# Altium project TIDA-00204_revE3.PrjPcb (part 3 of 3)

## Sheet TIDA-00204_revE3_Sitara_SC_0.SchDoc: =DocumentName
size 431 x 279 mm; Date: Not shown in title block; ApprovedBy: Not shown in title block; CheckedBy: Not shown in title block; Author: Not shown in title block; CompanyName: Not shown in title block; DrawnBy: K. Mogensen; Engineer: K. Mogensen; Organization: Not shown in title block; Address1: Not shown in title block; Address2: Not shown in title block; Address3: Not shown in title block; Address4: Not shown in title block; DocumentNumber: 7; Revision: Use project parameter SCH_Rev; SheetNumber: 7; SheetTotal: 10; PageSetup: Record=PageOptions¦CenterHorizontal=True¦CenterVertical=True¦PrintScale=0.62¦XCorrection=1.00¦YCorrection=1.00¦PrintKind=0¦BorderSize=5000000¦LeftOffset=0¦BottomOffset=0¦Orientation=2¦PaperLength=1000¦PaperWidth=1000¦Scale=100¦PaperSource=15¦PrintQuality=600¦MediaType=1¦DitherType=10¦PrintScaleMode=1¦PaperKind=Letter
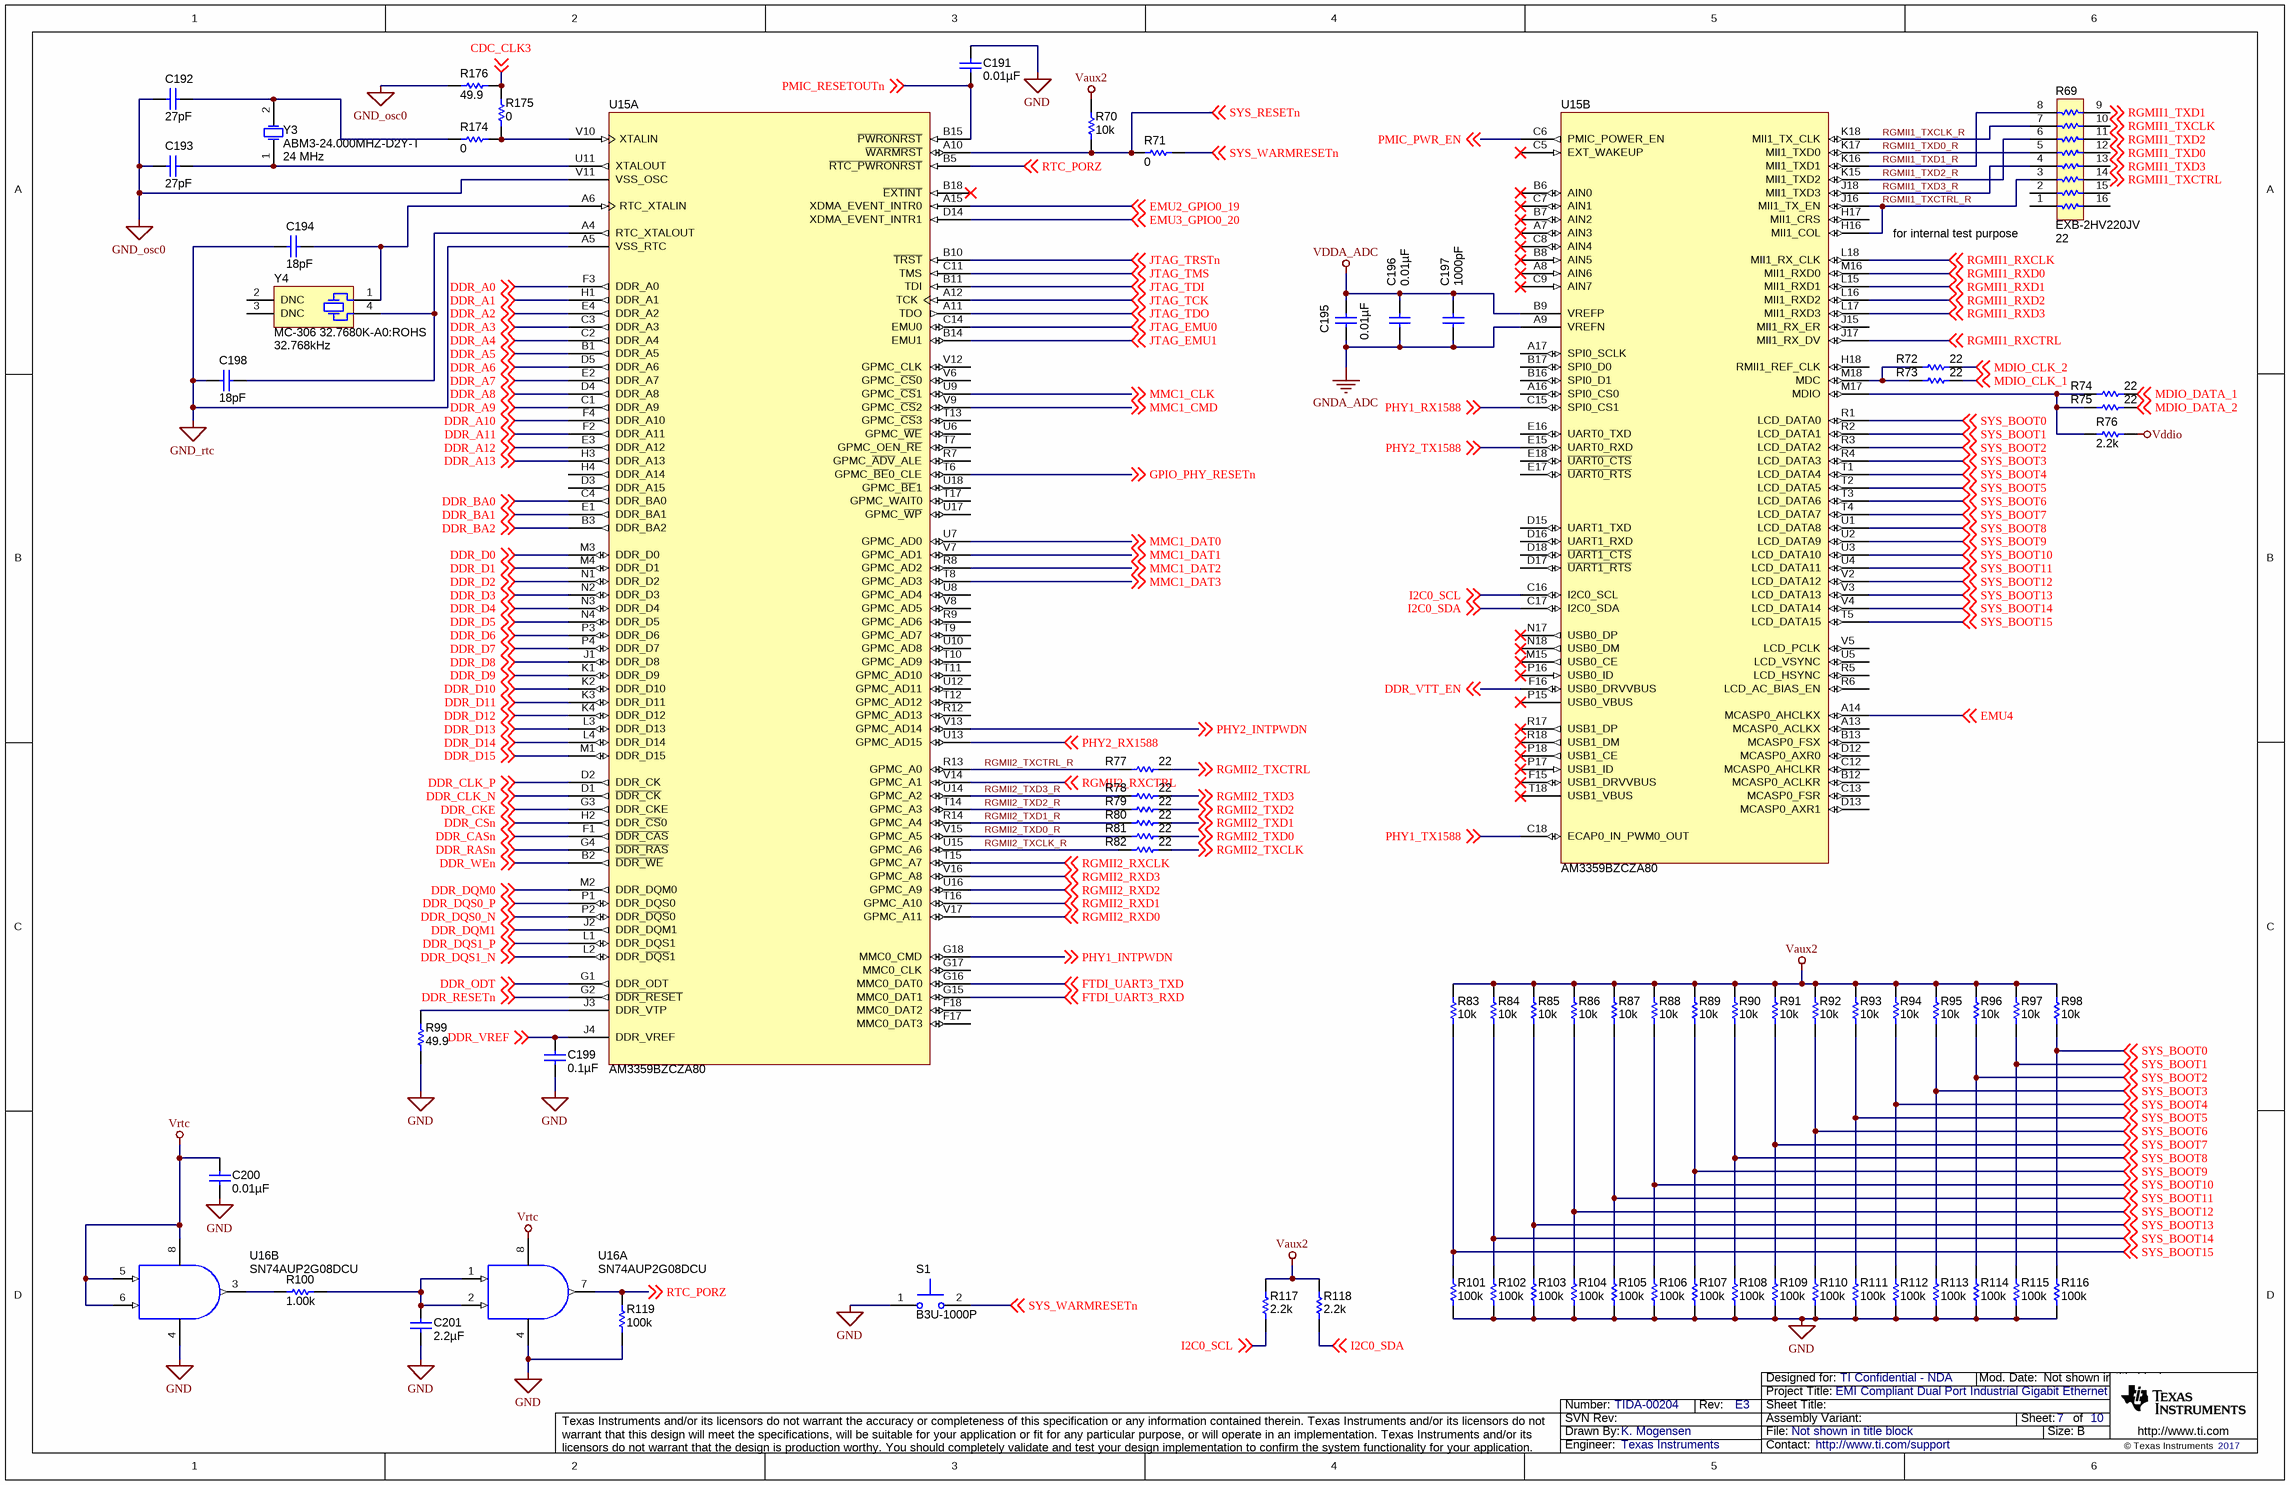
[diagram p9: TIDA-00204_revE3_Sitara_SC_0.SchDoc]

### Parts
C191  ValueDisplayed: 0.01µF  [0201]  (hidden comment: GRM033R71A103KA01D)
C192  ValueDisplayed: 27pF  [0402]  (hidden comment: GRM1555C1H270JA01D)
C193  ValueDisplayed: 27pF  [0402]  (hidden comment: GRM1555C1H270JA01D)
C194  ValueDisplayed: 18pF  [0402]  (hidden comment: GRM1555C1H180JA01D)
C195  ValueDisplayed: 0.01µF  [0201]  (hidden comment: GRM033R71A103KA01D)
C196  ValueDisplayed: 0.01µF  [0201]  (hidden comment: GRM033R71A103KA01D)
C197  ValueDisplayed: 1000pF  [0201]  (hidden comment: GRM033R71C102KA01D)
C198  ValueDisplayed: 18pF  [0402]  (hidden comment: GRM1555C1H180JA01D)
C199  ValueDisplayed: 0.1µF  [0402]  (hidden comment: GRM155R71A104KA01D)
C200  ValueDisplayed: 0.01µF  [0201]  (hidden comment: GRM033R71A103KA01D)
C201  ValueDisplayed: 2.2µF  [0603]  (hidden comment: GRM188R71A225KE15D)
R69  EXB-2HV220JV  ValueDisplayed: 22  [RESCAXS_EXB-2HV]
R70  ValueDisplayed: 10k  [0402]  (hidden comment: CRCW040210K0JNED)
R71  ValueDisplayed: 0  [0603]  (hidden comment: CRCW06030000Z0EA)
R72  ValueDisplayed: 22  [0402]  (hidden comment: CRCW040222R0JNED)
R73  ValueDisplayed: 22  [0402]  (hidden comment: CRCW040222R0JNED)
R74  ValueDisplayed: 22  [0402]  (hidden comment: CRCW040222R0JNED)
R75  ValueDisplayed: 22  [0402]  (hidden comment: CRCW040222R0JNED)
R76  ValueDisplayed: 2.2k  [0402]  (hidden comment: CRCW04022K20JNED)
R77  ValueDisplayed: 22  [0402]  (hidden comment: CRCW040222R0JNED)
R78  ValueDisplayed: 22  [0402]  (hidden comment: CRCW040222R0JNED)
R79  ValueDisplayed: 22  [0402]  (hidden comment: CRCW040222R0JNED)
R80  ValueDisplayed: 22  [0402]  (hidden comment: CRCW040222R0JNED)
R81  ValueDisplayed: 22  [0402]  (hidden comment: CRCW040222R0JNED)
R82  ValueDisplayed: 22  [0402]  (hidden comment: CRCW040222R0JNED)
R83  ValueDisplayed: 10k  [0402]  (hidden comment: CRCW040210K0JNED)
R84  ValueDisplayed: 10k  [0402]  (hidden comment: CRCW040210K0JNED)
R85  ValueDisplayed: 10k  [0402]  (hidden comment: CRCW040210K0JNED)
R86  ValueDisplayed: 10k  [0402]  (hidden comment: CRCW040210K0JNED)
R87  ValueDisplayed: 10k  [0402]  (hidden comment: CRCW040210K0JNED)
R88  ValueDisplayed: 10k  [0402]  (hidden comment: CRCW040210K0JNED)
R89  ValueDisplayed: 10k  [0402]  (hidden comment: CRCW040210K0JNED)
R90  ValueDisplayed: 10k  [0402]  (hidden comment: CRCW040210K0JNED)
R91  ValueDisplayed: 10k  [0402]  (hidden comment: CRCW040210K0JNED)
R92  ValueDisplayed: 10k  [0402]  (hidden comment: CRCW040210K0JNED)
R93  ValueDisplayed: 10k  [0402]  (hidden comment: CRCW040210K0JNED)
R94  ValueDisplayed: 10k  [0402]  (hidden comment: CRCW040210K0JNED)
R95  ValueDisplayed: 10k  [0402]  (hidden comment: CRCW040210K0JNED)
R96  ValueDisplayed: 10k  [0402]  (hidden comment: CRCW040210K0JNED)
R97  ValueDisplayed: 10k  [0402]  (hidden comment: CRCW040210K0JNED)
R98  ValueDisplayed: 10k  [0402]  (hidden comment: CRCW040210K0JNED)
R99  ValueDisplayed: 49.9  [0402]  (hidden comment: CRCW040249R9FKED)
R100  ValueDisplayed: 1.00k  [0402]  (hidden comment: CRCW04021K00FKED)
R101  ValueDisplayed: 100k  [0402]  (hidden comment: CRCW0402100KJNED)
R102  ValueDisplayed: 100k  [0402]  (hidden comment: CRCW0402100KJNED)
R103  ValueDisplayed: 100k  [0402]  (hidden comment: CRCW0402100KJNED)
R104  ValueDisplayed: 100k  [0402]  (hidden comment: CRCW0402100KJNED)
R105  ValueDisplayed: 100k  [0402]  (hidden comment: CRCW0402100KJNED)
R106  ValueDisplayed: 100k  [0402]  (hidden comment: CRCW0402100KJNED)
R107  ValueDisplayed: 100k  [0402]  (hidden comment: CRCW0402100KJNED)
R108  ValueDisplayed: 100k  [0402]  (hidden comment: CRCW0402100KJNED)
R109  ValueDisplayed: 100k  [0402]  (hidden comment: CRCW0402100KJNED)
R110  ValueDisplayed: 100k  [0402]  (hidden comment: CRCW0402100KJNED)
R111  ValueDisplayed: 100k  [0402]  (hidden comment: CRCW0402100KJNED)
R112  ValueDisplayed: 100k  [0402]  (hidden comment: CRCW0402100KJNED)
R113  ValueDisplayed: 100k  [0402]  (hidden comment: CRCW0402100KJNED)
R114  ValueDisplayed: 100k  [0402]  (hidden comment: CRCW0402100KJNED)
R115  ValueDisplayed: 100k  [0402]  (hidden comment: CRCW0402100KJNED)
R116  ValueDisplayed: 100k  [0402]  (hidden comment: CRCW0402100KJNED)
R117  ValueDisplayed: 2.2k  [0402]  (hidden comment: CRCW04022K20JNED)
R118  ValueDisplayed: 2.2k  [0402]  (hidden comment: CRCW04022K20JNED)
R119  ValueDisplayed: 100k  [0402]  (hidden comment: CRCW0402100KFKED)
R174  ValueDisplayed: 0  [0402]  (hidden comment: CRCW04020000Z0ED)
R175  ValueDisplayed: 0  [0402]  (hidden comment: CRCW04020000Z0ED)
R176  ValueDisplayed: 49.9  [0402]  (hidden comment: CRCW040249R9FKED)
S1  B3U-1000P  [SW_B3U-1000P]
U15  AM3359BZCZA80  [ZCZ0324A]  (parts A,B of 4)
U16  SN74AUP2G08DCU  [DCU0008A_N]  (parts A,B of 2)
Y3  ABM3-24.000MHZ-D2Y-T  Frequency: 24 MHz  [XTAL_ABM3]
Y4  MC-306 32.7680K-A0:ROHS  Frequency: 32.768kHz  [XTAL_MC-306]

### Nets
GND: C191.1 C199.2 C200.2 C201.2 R99.1 R101.1 R102.1 R103.1 R104.1 R105.1 R106.1 R107.1 R108.1 R109.1 R110.1 R111.1 R112.1 R113.1 R114.1 R115.1 R116.1 R119.1 S1.1 U16.4(V-)
GND_osc0: C192.2 C193.2 R176.1 U15.V11(VSS_OSC)
GND_rtc: C194.2 C198.2 U15.A5(VSS_RTC)
GNDA_ADC: C195.2 C196.2 C197.2 U15.A9(VREFN)
Vaux2: R70.2 R83.2 R84.2 R85.2 R86.2 R87.2 R88.2 R89.2 R90.2 R91.2 R92.2 R93.2 R94.2 R95.2 R96.2 R97.2 R98.2 R117.2 R118.2
VDDA_ADC: C195.1 C196.1 C197.1 U15.B9(VREFP)
Vddio: R76.2
Vrtc: C200.1 U16.5(2A) U16.6(2B) U16.8(V+)
CDC_CLK3: R175.2 R176.2 ; off-sheet CDC_CLK3
DDR_A0: U15.F3(DDR_A0) ; off-sheet DDR_A0
DDR_A1: U15.H1(DDR_A1) ; off-sheet DDR_A1
DDR_A2: U15.E4(DDR_A2) ; off-sheet DDR_A2
DDR_A3: U15.C3(DDR_A3) ; off-sheet DDR_A3
DDR_A4: U15.C2(DDR_A4) ; off-sheet DDR_A4
DDR_A5: U15.B1(DDR_A5) ; off-sheet DDR_A5
DDR_A6: U15.D5(DDR_A6) ; off-sheet DDR_A6
DDR_A7: U15.E2(DDR_A7) ; off-sheet DDR_A7
DDR_A8: U15.D4(DDR_A8) ; off-sheet DDR_A8
DDR_A9: U15.C1(DDR_A9) ; off-sheet DDR_A9
DDR_A10: U15.F4(DDR_A10) ; off-sheet DDR_A10
DDR_A11: U15.F2(DDR_A11) ; off-sheet DDR_A11
DDR_A12: U15.E3(DDR_A12) ; off-sheet DDR_A12
DDR_A13: U15.H3(DDR_A13) ; off-sheet DDR_A13
DDR_BA0: U15.C4(DDR_BA0) ; off-sheet DDR_BA0
DDR_BA1: U15.E1(DDR_BA1) ; off-sheet DDR_BA1
DDR_BA2: U15.B3(DDR_BA2) ; off-sheet DDR_BA2
DDR_CASn: U15.F1(~{DDR_CAS}) ; off-sheet DDR_CASn
DDR_CKE: U15.G3(DDR_CKE) ; off-sheet DDR_CKE
DDR_CLK_N: U15.D1(~{DDR_CK}) ; off-sheet DDR_CLK_N
DDR_CLK_P: U15.D2(DDR_CK) ; off-sheet DDR_CLK_P
DDR_CSn: U15.H2(DDR_~{CS}0) ; off-sheet DDR_CSn
DDR_D0: U15.M3(DDR_D0) ; off-sheet DDR_D0
DDR_D1: U15.M4(DDR_D1) ; off-sheet DDR_D1
DDR_D2: U15.N1(DDR_D2) ; off-sheet DDR_D2
DDR_D3: U15.N2(DDR_D3) ; off-sheet DDR_D3
DDR_D4: U15.N3(DDR_D4) ; off-sheet DDR_D4
DDR_D5: U15.N4(DDR_D5) ; off-sheet DDR_D5
DDR_D6: U15.P3(DDR_D6) ; off-sheet DDR_D6
DDR_D7: U15.P4(DDR_D7) ; off-sheet DDR_D7
DDR_D8: U15.J1(DDR_D8) ; off-sheet DDR_D8
DDR_D9: U15.K1(DDR_D9) ; off-sheet DDR_D9
DDR_D10: U15.K2(DDR_D10) ; off-sheet DDR_D10
DDR_D11: U15.K3(DDR_D11) ; off-sheet DDR_D11
DDR_D12: U15.K4(DDR_D12) ; off-sheet DDR_D12
DDR_D13: U15.L3(DDR_D13) ; off-sheet DDR_D13
DDR_D14: U15.L4(DDR_D14) ; off-sheet DDR_D14
DDR_D15: U15.M1(DDR_D15) ; off-sheet DDR_D15
DDR_DQM0: U15.M2(DDR_DQM0) ; off-sheet DDR_DQM0
DDR_DQM1: U15.J2(DDR_DQM1) ; off-sheet DDR_DQM1
DDR_DQS0_N: U15.P2(DDR_~{DQS}0) ; off-sheet DDR_DQS0_N
DDR_DQS0_P: U15.P1(DDR_DQS0) ; off-sheet DDR_DQS0_P
DDR_DQS1_N: U15.L2(DDR_~{DQS}1) ; off-sheet DDR_DQS1_N
DDR_DQS1_P: U15.L1(DDR_DQS1) ; off-sheet DDR_DQS1_P
DDR_ODT: U15.G1(DDR_ODT) ; off-sheet DDR_ODT
DDR_RASn: U15.G4(~{DDR_RAS}) ; off-sheet DDR_RASn
DDR_RESETn: U15.G2(~{DDR_RESET}) ; off-sheet DDR_RESETn
DDR_VREF: C199.1 U15.J4(DDR_VREF) ; off-sheet DDR_VREF
DDR_VTT_EN: U15.F16(USB0_DRVVBUS) ; off-sheet DDR_VTT_EN
DDR_WEn: U15.B2(~{DDR_WE}) ; off-sheet DDR_WEn
EMU2_GPIO0_19: U15.A15(XDMA_EVENT_INTR0) ; off-sheet EMU2_GPIO0_19
EMU3_GPIO0_20: U15.D14(XDMA_EVENT_INTR1) ; off-sheet EMU3_GPIO0_20
EMU4: U15.A14(MCASP0_AHCLKX) ; off-sheet EMU4
FTDI_UART3_RXD: U15.G15(MMC0_DAT1) ; off-sheet FTDI_UART3_RXD
FTDI_UART3_TXD: U15.G16(MMC0_DAT0) ; off-sheet FTDI_UART3_TXD
GPIO_PHY_RESETn: U15.T6(GPMC_~{BE}0_CLE) ; off-sheet GPIO_PHY_RESETn
I2C0_SCL: R117.1 U15.C16(I2C0_SCL) ; off-sheet I2C0_SCL
I2C0_SDA: R118.1 U15.C17(I2C0_SDA) ; off-sheet I2C0_SDA
JTAG_EMU0: U15.C14(EMU0) ; off-sheet JTAG_EMU0
JTAG_EMU1: U15.B14(EMU1) ; off-sheet JTAG_EMU1
JTAG_TCK: U15.A12(TCK) ; off-sheet JTAG_TCK
JTAG_TDI: U15.B11(TDI) ; off-sheet JTAG_TDI
JTAG_TDO: U15.A11(TDO) ; off-sheet JTAG_TDO
JTAG_TMS: U15.C11(TMS) ; off-sheet JTAG_TMS
JTAG_TRSTn: U15.B10(~{TRST}) ; off-sheet JTAG_TRSTn
MDIO_CLK_1: R73.2 ; off-sheet MDIO_CLK_1
MDIO_CLK_2: R72.2 ; off-sheet MDIO_CLK_2
MDIO_DATA_1: R74.2 ; off-sheet MDIO_DATA_1
MDIO_DATA_2: R75.2 ; off-sheet MDIO_DATA_2
MMC1_CLK: U15.U9(GPMC_~{CS}1) ; off-sheet MMC1_CLK
MMC1_CMD: U15.V9(GPMC_~{CS}2) ; off-sheet MMC1_CMD
MMC1_DAT0: U15.U7(GPMC_AD0) ; off-sheet MMC1_DAT0
MMC1_DAT1: U15.V7(GPMC_AD1) ; off-sheet MMC1_DAT1
MMC1_DAT2: U15.R8(GPMC_AD2) ; off-sheet MMC1_DAT2
MMC1_DAT3: U15.T8(GPMC_AD3) ; off-sheet MMC1_DAT3
PHY1_INTPWDN: U15.G18(MMC0_CMD) ; off-sheet PHY1_INTPWDN
PHY1_RX1588: U15.C15(SPI0_CS1) ; off-sheet PHY1_RX1588
PHY1_TX1588: U15.C18(ECAP0_IN_PWM0_OUT) ; off-sheet PHY1_TX1588
PHY2_INTPWDN: U15.V13(GPMC_AD14) ; off-sheet PHY2_INTPWDN
PHY2_RX1588: U15.U13(GPMC_AD15) ; off-sheet PHY2_RX1588
PHY2_TX1588: U15.E15(UART0_RXD) ; off-sheet PHY2_TX1588
PMIC_PWR_EN: U15.C6(PMIC_POWER_EN) ; off-sheet PMIC_PWR_EN
PMIC_RESETOUTn: C191.2 U15.B15(~{PWRONRST}) ; off-sheet PMIC_RESETOUTn
RGMII1_RXCLK: U15.L18(MII1_RX_CLK) ; off-sheet RGMII1_RXCLK
RGMII1_RXCTRL: U15.J17(MII1_RX_DV) ; off-sheet RGMII1_RXCTRL
RGMII1_RXD0: U15.M16(MII1_RXD0) ; off-sheet RGMII1_RXD0
RGMII1_RXD1: U15.L15(MII1_RXD1) ; off-sheet RGMII1_RXD1
RGMII1_RXD2: U15.L16(MII1_RXD2) ; off-sheet RGMII1_RXD2
RGMII1_RXD3: U15.L17(MII1_RXD3) ; off-sheet RGMII1_RXD3
RGMII1_TXCLK: R69.10 ; off-sheet RGMII1_TXCLK
RGMII1_TXCLK_R: R69.7 U15.K18(MII1_TX_CLK)
RGMII1_TXCTRL: R69.14 ; off-sheet RGMII1_TXCTRL
RGMII1_TXCTRL_R: R69.3 U15.H16(MII1_COL) U15.J16(MII1_TX_EN)
RGMII1_TXD0: R69.12 ; off-sheet RGMII1_TXD0
RGMII1_TXD0_R: R69.5 U15.K17(MII1_TXD0)
RGMII1_TXD1: R69.9 ; off-sheet RGMII1_TXD1
RGMII1_TXD1_R: R69.8 U15.K16(MII1_TXD1)
RGMII1_TXD2: R69.11 ; off-sheet RGMII1_TXD2
RGMII1_TXD2_R: R69.6 U15.K15(MII1_TXD2)
RGMII1_TXD3: R69.13 ; off-sheet RGMII1_TXD3
RGMII1_TXD3_R: R69.4 U15.J18(MII1_TXD3)
RGMII2_RXCLK: U15.T15(GPMC_A7) ; off-sheet RGMII2_RXCLK
RGMII2_RXCTRL: U15.V14(GPMC_A1) ; off-sheet RGMII2_RXCTRL
RGMII2_RXD0: U15.V17(GPMC_A11) ; off-sheet RGMII2_RXD0
RGMII2_RXD1: U15.T16(GPMC_A10) ; off-sheet RGMII2_RXD1
RGMII2_RXD2: U15.U16(GPMC_A9) ; off-sheet RGMII2_RXD2
RGMII2_RXD3: U15.V16(GPMC_A8) ; off-sheet RGMII2_RXD3
RGMII2_TXCLK: R82.2 ; off-sheet RGMII2_TXCLK
RGMII2_TXCLK_R: R82.1 U15.U15(GPMC_A6)
RGMII2_TXCTRL: R77.2 ; off-sheet RGMII2_TXCTRL
RGMII2_TXCTRL_R: R77.1 U15.R13(GPMC_A0)
RGMII2_TXD0: R81.2 ; off-sheet RGMII2_TXD0
RGMII2_TXD0_R: R81.1 U15.V15(GPMC_A5)
RGMII2_TXD1: R80.2 ; off-sheet RGMII2_TXD1
RGMII2_TXD1_R: R80.1 U15.R14(GPMC_A4)
RGMII2_TXD2: R79.2 ; off-sheet RGMII2_TXD2
RGMII2_TXD2_R: R79.1 U15.T14(GPMC_A3)
RGMII2_TXD3: R78.2 ; off-sheet RGMII2_TXD3
RGMII2_TXD3_R: R78.1 U15.U14(GPMC_A2)
RTC_PORZ: R119.2 U15.B5(~{RTC_PWRONRST}) U16.7(1Y) ; off-sheet RTC_PORZ
SYS_BOOT0: R98.1 R116.2 U15.R1(LCD_DATA0) ; off-sheet SYS_BOOT0
SYS_BOOT1: R97.1 R115.2 U15.R2(LCD_DATA1) ; off-sheet SYS_BOOT1
SYS_BOOT2: R96.1 R114.2 U15.R3(LCD_DATA2) ; off-sheet SYS_BOOT2
SYS_BOOT3: R95.1 R113.2 U15.R4(LCD_DATA3) ; off-sheet SYS_BOOT3
SYS_BOOT4: R94.1 R112.2 U15.T1(LCD_DATA4) ; off-sheet SYS_BOOT4
SYS_BOOT5: R93.1 R111.2 U15.T2(LCD_DATA5) ; off-sheet SYS_BOOT5
SYS_BOOT6: R92.1 R110.2 U15.T3(LCD_DATA6) ; off-sheet SYS_BOOT6
SYS_BOOT7: R91.1 R109.2 U15.T4(LCD_DATA7) ; off-sheet SYS_BOOT7
SYS_BOOT8: R90.1 R108.2 U15.U1(LCD_DATA8) ; off-sheet SYS_BOOT8
SYS_BOOT9: R89.1 R107.2 U15.U2(LCD_DATA9) ; off-sheet SYS_BOOT9
SYS_BOOT10: R88.1 R106.2 U15.U3(LCD_DATA10) ; off-sheet SYS_BOOT10
SYS_BOOT11: R87.1 R105.2 U15.U4(LCD_DATA11) ; off-sheet SYS_BOOT11
SYS_BOOT12: R86.1 R104.2 U15.V2(LCD_DATA12) ; off-sheet SYS_BOOT12
SYS_BOOT13: R85.1 R103.2 U15.V3(LCD_DATA13) ; off-sheet SYS_BOOT13
SYS_BOOT14: R84.1 R102.2 U15.V4(LCD_DATA14) ; off-sheet SYS_BOOT14
SYS_BOOT15: R83.1 R101.2 U15.T5(LCD_DATA15) ; off-sheet SYS_BOOT15
SYS_RESETn: R70.1 R71.1 U15.A10(~{WARMRST}) ; off-sheet SYS_RESETn
SYS_WARMRESETn: R71.2 S1.2 ; off-sheet SYS_WARMRESETn
NetC192_1: C192.1 R174.2 Y3.2(OSC2)
NetC193_1: C193.1 U15.U11(XTALOUT) Y3.1(OSC1)
NetC194_1: C194.1 U15.A6(RTC_XTALIN) Y4.1
NetC198_1: C198.1 U15.A4(RTC_XTALOUT) Y4.4
NetC201_1: C201.1 R100.1 U16.1(1A) U16.2(1B)
NetR72_1: R72.1 R73.1 U15.M18(MDC)
NetR74_1: R74.1 R75.1 R76.1 U15.M17(MDIO)
NetR99_2: R99.2 U15.J3(DDR_VTP)
NetR100_2: R100.2 U16.3(2Y)
NetR174_1: R174.1 R175.1 U15.V10(XTALIN)

Not connected (* = marked no-connect by the designer): R69 1 2 15 16; U15 A7(AIN3)* A8(AIN6)* A13(MCASP0_ACLKX) A16(SPI0_CS0) A17(SPI0_SCLK) B6(AIN0)* B7(AIN2)* B8(AIN5)* B12(MCASP0_ACLKR) B13(MCASP0_FSX) B16(SPI0_D1) B17(SPI0_D0) B18(~{EXTINT})* C5(EXT_WAKEUP)* C7(AIN1)* C8(AIN4)* C9(AIN7)* C12(MCASP0_AHCLKR) C13(MCASP0_FSR) D3(DDR_A15) D12(MCASP0_AXR0) D13(MCASP0_AXR1) D15(UART1_TXD) D16(UART1_RXD) D17(~{UART1_RTS}) D18(~{UART1_CTS}) E16(UART0_TXD) E17(~{UART0_RTS}) E18(~{UART0_CTS}) F15(USB1_DRVVBUS)* F17(MMC0_DAT3) F18(MMC0_DAT2) G17(MMC0_CLK) H4(DDR_A14) H17(MII1_CRS) H18(RMII1_REF_CLK) J15(MII1_RX_ER) M15(USB0_CE)* N17(USB0_DP)* N18(USB0_DM)* P15(USB0_VBUS)* P16(USB0_ID)* P17(USB1_ID)* P18(USB1_CE)* R5(LCD_HSYNC) R6(LCD_AC_BIAS_EN) R7(GPMC_~{ADV}_ALE) R9(GPMC_AD6) R12(GPMC_AD13) R17(USB1_DP)* R18(USB1_DM)* T7(GPMC_OEN_~{RE}) T9(GPMC_AD7) T10(GPMC_AD9) T11(GPMC_AD10) T12(GPMC_AD12) T13(GPMC_~{CS}3) T17(GPMC_WAIT0) T18(USB1_VBUS)* U5(LCD_VSYNC) U6(GPMC_~{WE}) U8(GPMC_AD4) U10(GPMC_AD8) U12(GPMC_AD11) U17(GPMC_~{WP}) U18(GPMC_~{BE}1) V5(LCD_PCLK) V6(GPMC_~{CS}0) V8(GPMC_AD5) V12(GPMC_CLK); Y4 2(DNC) 3(DNC)

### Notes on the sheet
- for internal test purpose

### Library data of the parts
C191 C195 C196 C200 = GRM033R71A103KA01D: CAP, CERM, 0.01 µF, 10 V, +/- 10%, X7R, 0201; Manufacturer: MuRata; Polarized: N; CompType: Capacitor; Value: 0.01uF; U/M: EA; Cap_F: 0.00000001; Tolerance_%: 10; Value1: Unknown; Value2: 10V; TaMin_C: -55; TaMax_C: 125
C192 C193 = GRM1555C1H270JA01D: CAP, CERM, 27 pF, 50 V, +/- 5%, C0G/NP0, 0402; Manufacturer: MuRata; Polarized: N; CompType: Capacitor; Value: 27pF; U/M: EA; Cap_F: 0.000000000027; Tolerance_%: 5; Value1: Unknown; VDC_V: 50; Value2: 50V; TaMin_C: -55; TaMax_C: 125
C194 C198 = GRM1555C1H180JA01D: CAP, CERM, 18 pF, 50 V, +/- 5%, C0G/NP0, 0402; Manufacturer: MuRata; Polarized: N; CompType: Capacitor; Value: 18pF; U/M: EA; Cap_F: 0.000000000018; Tolerance_%: 5; Value1: Unknown; VDC_V: 50; Value2: 50V; TaMin_C: -55; TaMax_C: 125
C197 = GRM033R71C102KA01D: CAP, CERM, 1000 pF, 16 V, +/- 10%, X7R, 0201; Manufacturer: MuRata; Polarized: N; CompType: Capacitor; Value: 1000pF; U/M: EA; Cap_F: 0.000000001; Tolerance_%: 10; Value1: Unknown; VDC_V: 16; Value2: 16V; TaMin_C: -55; TaMax_C: 125
C199 = GRM155R71A104KA01D: CAP, CERM, 0.1 µF, 10 V, +/- 10%, X7R, 0402; Manufacturer: MuRata; Polarized: N; CompType: Capacitor; Value: 0.1uF; U/M: EA; Cap_F: 0.0000001; Tolerance_%: 10; Value1: Unknown; Value2: 10V; TaMin_C: -55; TaMax_C: 125
C201 = GRM188R71A225KE15D: CAP, CERM, 2.2 µF, 10 V, +/- 10%, X7R, 0603; Manufacturer: MuRata; Polarized: N; CompType: Capacitor; Value: 2.2uF; U/M: EA; Cap_F: 0.0000022; Tolerance_%: 10; ESR_ohm: 0.009; Value1: 0.009 ohm; Value2: 10V; TaMin_C: -55; TaMax_C: 125
R69 = EXB-2HV220JV: RES, 22, 5%, 0.0625 W, Resistor Array - 8x1; Manufacturer: Panasonic; SymbolCreator: a0411947; Value: 22; Value_Code: 22R0; Tolerance_%: 5; Power_W: 0.0625; TempCo: 200 ppm/C; EIA_Code: E24; U/M: EA
R70 R83-R98 = CRCW040210K0JNED: RES, 10 k, 5%, 0.063 W, 0402; Manufacturer: Vishay-Dale; CompType: Resistor; Value: 10k; Res_ohm: 10000; Value_Code: 10k0; Tolerance_%: 5; Power_W: 0.063; Value2: 0.063W; VDC_V: 50; TempCo: 200 ppm/C; EIA_Code: E24; U/M: EA
R71 = CRCW06030000Z0EA: RES, 0, 5%, 0.1 W, 0603; Manufacturer: Vishay-Dale; CompType: Resistor; Value: 0; Value_Code: 0000; Tolerance_%: 5; Power_W: 0.1; Value2: 0.1W; VDC_V: 75; TempCo: 200 ppm/C; EIA_Code: E24; U/M: EA
R72-R75 R77-R82 = CRCW040222R0JNED: RES, 22, 5%, 0.063 W, 0402; Manufacturer: Vishay-Dale; CompType: Resistor; Value: 22; Value_Code: 22R0; Tolerance_%: 5; Power_W: 0.063; Value2: 0.063W; VDC_V: 50; TempCo: 200 ppm/C; EIA_Code: E24; U/M: EA
R76 R117 R118 = CRCW04022K20JNED: RES, 2.2 k, 5%, 0.063 W, 0402; Manufacturer: Vishay-Dale; CompType: Resistor; Value: 2.2k; Res_ohm: 2200; Value_Code: 2k20; Tolerance_%: 5; Power_W: 0.063; Value2: 0.063W; VDC_V: 50; TempCo: 200 ppm/C; EIA_Code: E24; U/M: EA
R99 R176 = CRCW040249R9FKED: RES, 49.9, 1%, 0.063 W, 0402; Manufacturer: Vishay-Dale; CompType: Resistor; Value: 49.9; Value_Code: 49R9; Tolerance_%: 1; Power_W: 0.063; Value2: 0.063W; VDC_V: 50; TempCo: 100 ppm/C; EIA_Code: E96; U/M: EA
R100 = CRCW04021K00FKED: RES, 1.00 k, 1%, 0.063 W, 0402; Manufacturer: Vishay-Dale; CompType: Resistor; Value: 1.00k; Res_ohm: 1000; Value_Code: 1k00; Tolerance_%: 1; Power_W: 0.063; Value2: 0.063W; VDC_V: 50; TempCo: 100 ppm/C; EIA_Code: E96; U/M: EA
R101-R116 = CRCW0402100KJNED: RES, 100 k, 5%, 0.063 W, 0402; Manufacturer: Vishay-Dale; CompType: Resistor; Value: 100k; Res_ohm: 100000; Tolerance_%: 5; Power_W: 0.063; Value2: 0.063W; VDC_V: 50; TempCo: 200 ppm/C; EIA_Code: E24; U/M: EA
R119 = CRCW0402100KFKED: RES, 100 k, 1%, 0.063 W, 0402; Manufacturer: Vishay-Dale; CompType: Resistor; Value: 100k; Res_ohm: 100000; Tolerance_%: 1; Power_W: 0.063; Value2: 0.063W; VDC_V: 50; TempCo: 100 ppm/C; EIA_Code: E96; U/M: EA
R174 R175 = CRCW04020000Z0ED: RES, 0, 5%, 0.063 W, 0402; Manufacturer: Vishay-Dale; CompType: Resistor; Value: 0; Value_Code: 0000; Tolerance_%: 5; Power_W: 0.063; Value2: 0.063W; VDC_V: 50; TempCo: 200 ppm/C; EIA_Code: E24; U/M: EA
S1 = B3U-1000P: SWITCH TACTILE SPST-NO 0.05A 12V; Manufacturer: Omron Electronic Components; SymbolCreator: a0412235; VDC_V: 12; SwitchFunction: Off-Mom; PositionCount: 1; CurrentRating_mA: 50
U15 = AM3359BZCZA80: Sitara Processors, ZCZ0324A; Alternate Manufacturer: None; Manufacturer: Texas Instruments; SymbolCreator: Altium; CompType: IC; U/M: EA
U16 = SN74AUP2G08DCU: LOW-POWER DUAL 2-INPUT POSITIVE-AND GATE, DCU0008A; Manufacturer: Texas Instruments; SymbolCreator: Altium; CompType: IC; U/M: EA
Y3 = ABM3-24.000MHZ-D2Y-T: Crystal, 24 MHz, 18 pF, SMD; Manufacturer: Abracon Corportation; SymbolCreator: a0412235; U/M: EA; TaMin_C: -40; TaMax_C: 85; Frequency Stability: ±30ppm
Y4 = MC-306 32.7680K-A0:ROHS: Crystal, 32.768kHz, 12.5pF, SMD; Manufacturer: Epson; SymbolCreator: a0411947; U/M: EA; TaMin_C: -40; TaMax_C: 85; Frequency Stability: ±20ppm

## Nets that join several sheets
GND: TIDA-00204_revE3_JTAGUSB (44 pins), TIDA-00204_revE3_Memory (64 pins), TIDA-00204_revE3_PHY_1 (47 pins), TIDA-00204_revE3_PHY_2 (57 pins), TIDA-00204_revE3_PS_0 (23 pins), TIDA-00204_revE3_PS_1 (17 pins), TIDA-00204_revE3_PS_2 (34 pins), TIDA-00204_revE3_Sitara_PS (129 pins), TIDA-00204_revE3_Sitara_SC_0 (24 pins)
GND_osc0: TIDA-00204_revE3_Sitara_PS (C147.2), TIDA-00204_revE3_Sitara_SC_0 (C192.2 C193.2 R176.1 U15.V11)
GNDA_ADC: TIDA-00204_revE3_Sitara_PS (C144.2 L7.1 U15.E8), TIDA-00204_revE3_Sitara_SC_0 (C195.2 C196.2 C197.2 U15.A9)
V5__DC_Sitara: TIDA-00204_revE3_PS_0 (J1.2 R3.2), TIDA-00204_revE3_PS_1 (C22.2 R8.1 R10.1 U5.4), TIDA-00204_revE3_PS_2 (20 pins)
V11phy: TIDA-00204_revE3_PHY_1 (10 pins), TIDA-00204_revE3_PHY_2 (10 pins), TIDA-00204_revE3_PS_1 (C23.1 U5.1)
V18CDC: TIDA-00204_revE3_PHY_2 (L13.1 R169.2 R177.2 R178.2), TIDA-00204_revE3_PS_2 (C260.1 U13.7)
V25phy: TIDA-00204_revE3_PHY_1 (6 pins), TIDA-00204_revE3_PHY_2 (6 pins), TIDA-00204_revE3_PS_1 (R9.2 R13.2)
Vaux1: TIDA-00204_revE3_PS_2 (C95.1 U13.46), TIDA-00204_revE3_Sitara_PS (C134.1 C135.1 U15.N16 U15.R16)
Vaux2: TIDA-00204_revE3_PS_1 (U2.5), TIDA-00204_revE3_PS_2 (C96.1 U13.48), TIDA-00204_revE3_Sitara_PS (34 pins), TIDA-00204_revE3_Sitara_SC_0 (19 pins)
Vaux33: TIDA-00204_revE3_Memory (C233.1 R135.2 R137.2 U20.10), TIDA-00204_revE3_PS_2 (C93.1 R66.2 U13.4 U13.12), TIDA-00204_revE3_Sitara_PS (C136.1 C137.1 U15.N15 U15.R15)
Vdac: TIDA-00204_revE3_PS_2 (C98.1 U13.22), TIDA-00204_revE3_Sitara_PS (12 pins)
Vdd1_smps: TIDA-00204_revE3_PS_2 (C86.1 L3.2 U13.32), TIDA-00204_revE3_Sitara_PS (14 pins)
Vdd2_smps: TIDA-00204_revE3_PS_2 (C88.1 L4.2 U13.44), TIDA-00204_revE3_Sitara_PS (35 pins)
VDDA_ADC: TIDA-00204_revE3_Sitara_PS (C144.1 L6.1 U15.D8), TIDA-00204_revE3_Sitara_SC_0 (C195.1 C196.1 C197.1 U15.B9)
Vddio: TIDA-00204_revE3_JTAGUSB (24 pins), TIDA-00204_revE3_Memory (C207.2 U19.8), TIDA-00204_revE3_PHY_1 (14 pins), TIDA-00204_revE3_PHY_2 (13 pins), TIDA-00204_revE3_PS_1 (J3.2 R12.1), TIDA-00204_revE3_Sitara_SC_0 (R76.2)
Vdds_DDR: TIDA-00204_revE3_Memory (38 pins), TIDA-00204_revE3_PS_2 (C90.1 L5.2 U13.16), TIDA-00204_revE3_Sitara_PS (29 pins)
Vdig2: TIDA-00204_revE3_PS_2 (C92.1 U13.5), TIDA-00204_revE3_Sitara_PS (12 pins)
Vmmc: TIDA-00204_revE3_Memory (11 pins), TIDA-00204_revE3_PS_2 (C94.1 U13.2), TIDA-00204_revE3_Sitara_PS (10 pins)
Vpll: TIDA-00204_revE3_PS_2 (C97.1 U13.24), TIDA-00204_revE3_Sitara_PS (L6.2)
Vrtc: TIDA-00204_revE3_PS_2 (C101.1 U14.1), TIDA-00204_revE3_Sitara_PS (C146.1 U15.D7), TIDA-00204_revE3_Sitara_SC_0 (C200.1 U16.5 U16.6 U16.8)
CDC_CLK1: TIDA-00204_revE3_PHY_1 (R171.2), TIDA-00204_revE3_PHY_2 (R182.2)
CDC_CLK3: TIDA-00204_revE3_PHY_2 (R167.2), TIDA-00204_revE3_Sitara_SC_0 (R175.2 R176.2)
DDR_A0: TIDA-00204_revE3_Memory (R128.1 U17.N3), TIDA-00204_revE3_Sitara_SC_0 (U15.F3)
DDR_A1: TIDA-00204_revE3_Memory (R128.3 U17.P7), TIDA-00204_revE3_Sitara_SC_0 (U15.H1)
DDR_A2: TIDA-00204_revE3_Memory (R133.7 U17.P3), TIDA-00204_revE3_Sitara_SC_0 (U15.E4)
DDR_A3: TIDA-00204_revE3_Memory (R133.4 U17.N2), TIDA-00204_revE3_Sitara_SC_0 (U15.C3)
DDR_A4: TIDA-00204_revE3_Memory (R128.6 U17.P8), TIDA-00204_revE3_Sitara_SC_0 (U15.C2)
DDR_A5: TIDA-00204_revE3_Memory (R133.6 U17.P2), TIDA-00204_revE3_Sitara_SC_0 (U15.B1)
DDR_A6: TIDA-00204_revE3_Memory (R130.2 U17.R8), TIDA-00204_revE3_Sitara_SC_0 (U15.D5)
DDR_A7: TIDA-00204_revE3_Memory (R130.8 U17.R2), TIDA-00204_revE3_Sitara_SC_0 (U15.E2)
DDR_A8: TIDA-00204_revE3_Memory (R130.1 U17.T8), TIDA-00204_revE3_Sitara_SC_0 (U15.D4)
DDR_A9: TIDA-00204_revE3_Memory (R130.6 U17.R3), TIDA-00204_revE3_Sitara_SC_0 (U15.C1)
DDR_A10: TIDA-00204_revE3_Memory (R130.5 U17.L7), TIDA-00204_revE3_Sitara_SC_0 (U15.F4)
DDR_A11: TIDA-00204_revE3_Memory (R130.4 U17.R7), TIDA-00204_revE3_Sitara_SC_0 (U15.F2)
DDR_A12: TIDA-00204_revE3_Memory (R128.4 U17.N7), TIDA-00204_revE3_Sitara_SC_0 (U15.E3)
DDR_A13: TIDA-00204_revE3_Memory (R130.7 U17.T3), TIDA-00204_revE3_Sitara_SC_0 (U15.H3)
DDR_BA0: TIDA-00204_revE3_Memory (R133.3 U17.M2), TIDA-00204_revE3_Sitara_SC_0 (U15.C4)
DDR_BA1: TIDA-00204_revE3_Memory (R128.5 U17.N8), TIDA-00204_revE3_Sitara_SC_0 (U15.E1)
DDR_BA2: TIDA-00204_revE3_Memory (R133.8 U17.M3), TIDA-00204_revE3_Sitara_SC_0 (U15.B3)
DDR_CASn: TIDA-00204_revE3_Memory (R133.5 U17.K3), TIDA-00204_revE3_Sitara_SC_0 (U15.F1)
DDR_CKE: TIDA-00204_revE3_Memory (R131.2 U17.K9), TIDA-00204_revE3_Sitara_SC_0 (U15.G3)
DDR_CLK_N: TIDA-00204_revE3_Memory (R127.1 U17.K7), TIDA-00204_revE3_Sitara_SC_0 (U15.D1)
DDR_CLK_P: TIDA-00204_revE3_Memory (R126.1 U17.J7), TIDA-00204_revE3_Sitara_SC_0 (U15.D2)
DDR_CSn: TIDA-00204_revE3_Memory (R133.1 U17.L2), TIDA-00204_revE3_Sitara_SC_0 (U15.H2)
DDR_D0: TIDA-00204_revE3_Memory (U17.H7), TIDA-00204_revE3_Sitara_SC_0 (U15.M3)
DDR_D1: TIDA-00204_revE3_Memory (U17.F8), TIDA-00204_revE3_Sitara_SC_0 (U15.M4)
DDR_D2: TIDA-00204_revE3_Memory (U17.G2), TIDA-00204_revE3_Sitara_SC_0 (U15.N1)
DDR_D3: TIDA-00204_revE3_Memory (U17.F2), TIDA-00204_revE3_Sitara_SC_0 (U15.N2)
DDR_D4: TIDA-00204_revE3_Memory (U17.H3), TIDA-00204_revE3_Sitara_SC_0 (U15.N3)
DDR_D5: TIDA-00204_revE3_Memory (U17.H8), TIDA-00204_revE3_Sitara_SC_0 (U15.N4)
DDR_D6: TIDA-00204_revE3_Memory (U17.E3), TIDA-00204_revE3_Sitara_SC_0 (U15.P3)
DDR_D7: TIDA-00204_revE3_Memory (U17.F7), TIDA-00204_revE3_Sitara_SC_0 (U15.P4)
DDR_D8: TIDA-00204_revE3_Memory (U17.C3), TIDA-00204_revE3_Sitara_SC_0 (U15.J1)
DDR_D9: TIDA-00204_revE3_Memory (U17.C2), TIDA-00204_revE3_Sitara_SC_0 (U15.K1)
DDR_D10: TIDA-00204_revE3_Memory (U17.D7), TIDA-00204_revE3_Sitara_SC_0 (U15.K2)
DDR_D11: TIDA-00204_revE3_Memory (U17.C8), TIDA-00204_revE3_Sitara_SC_0 (U15.K3)
DDR_D12: TIDA-00204_revE3_Memory (U17.A3), TIDA-00204_revE3_Sitara_SC_0 (U15.K4)
DDR_D13: TIDA-00204_revE3_Memory (U17.A2), TIDA-00204_revE3_Sitara_SC_0 (U15.L3)
DDR_D14: TIDA-00204_revE3_Memory (U17.A7), TIDA-00204_revE3_Sitara_SC_0 (U15.L4)
DDR_D15: TIDA-00204_revE3_Memory (U17.B8), TIDA-00204_revE3_Sitara_SC_0 (U15.M1)
DDR_DQM0: TIDA-00204_revE3_Memory (U17.E7), TIDA-00204_revE3_Sitara_SC_0 (U15.M2)
DDR_DQM1: TIDA-00204_revE3_Memory (U17.D3), TIDA-00204_revE3_Sitara_SC_0 (U15.J2)
DDR_DQS0_N: TIDA-00204_revE3_Memory (U17.G3), TIDA-00204_revE3_Sitara_SC_0 (U15.P2)
DDR_DQS0_P: TIDA-00204_revE3_Memory (U17.F3), TIDA-00204_revE3_Sitara_SC_0 (U15.P1)
DDR_DQS1_N: TIDA-00204_revE3_Memory (U17.B7), TIDA-00204_revE3_Sitara_SC_0 (U15.L2)
DDR_DQS1_P: TIDA-00204_revE3_Memory (U17.C7), TIDA-00204_revE3_Sitara_SC_0 (U15.L1)
DDR_ODT: TIDA-00204_revE3_Memory (R133.2 U17.K1), TIDA-00204_revE3_Sitara_SC_0 (U15.G1)
DDR_RASn: TIDA-00204_revE3_Memory (R134.1 U17.J3), TIDA-00204_revE3_Sitara_SC_0 (U15.G4)
DDR_RESETn: TIDA-00204_revE3_Memory (R129.1 U17.T2), TIDA-00204_revE3_Sitara_SC_0 (U15.G2)
DDR_VREF: TIDA-00204_revE3_Memory (6 pins), TIDA-00204_revE3_Sitara_SC_0 (C199.1 U15.J4)
DDR_VTT_EN: TIDA-00204_revE3_Memory (R137.1 U20.7), TIDA-00204_revE3_Sitara_SC_0 (U15.F16)
DDR_WEn: TIDA-00204_revE3_Memory (R128.2 U17.L3), TIDA-00204_revE3_Sitara_SC_0 (U15.B2)
EMU2_GPIO0_19: TIDA-00204_revE3_JTAGUSB (R161.1), TIDA-00204_revE3_Sitara_SC_0 (U15.A15)
EMU3_GPIO0_20: TIDA-00204_revE3_JTAGUSB (R162.1), TIDA-00204_revE3_Sitara_SC_0 (U15.D14)
EMU4: TIDA-00204_revE3_JTAGUSB (R163.1), TIDA-00204_revE3_Sitara_SC_0 (U15.A14)
FTDI_UART3_RXD: TIDA-00204_revE3_JTAGUSB (U22.38), TIDA-00204_revE3_Sitara_SC_0 (U15.G15)
FTDI_UART3_TXD: TIDA-00204_revE3_JTAGUSB (U22.39), TIDA-00204_revE3_Sitara_SC_0 (U15.G16)
GPIO_PHY_RESETn: TIDA-00204_revE3_PHY_1 (R38.1 U11.1), TIDA-00204_revE3_Sitara_SC_0 (U15.T6)
I2C0_SCL: TIDA-00204_revE3_Memory (U19.6), TIDA-00204_revE3_PS_2 (U13.9), TIDA-00204_revE3_Sitara_SC_0 (R117.1 U15.C16)
I2C0_SDA: TIDA-00204_revE3_Memory (U19.5), TIDA-00204_revE3_PS_2 (U13.8), TIDA-00204_revE3_Sitara_SC_0 (R118.1 U15.C17)
JTAG_EMU0: TIDA-00204_revE3_JTAGUSB (J8.13 R144.2 R152.1), TIDA-00204_revE3_Sitara_SC_0 (U15.C14)
JTAG_EMU1: TIDA-00204_revE3_JTAGUSB (J8.14 R146.1 R147.2), TIDA-00204_revE3_Sitara_SC_0 (U15.B14)
JTAG_TCK: TIDA-00204_revE3_JTAGUSB (R139.2 R159.1 R160.1), TIDA-00204_revE3_Sitara_SC_0 (U15.A12)
JTAG_TDI: TIDA-00204_revE3_JTAGUSB (J8.3 R140.2), TIDA-00204_revE3_Sitara_SC_0 (U15.B11)
JTAG_TDO: TIDA-00204_revE3_JTAGUSB (J8.7 R141.2), TIDA-00204_revE3_Sitara_SC_0 (U15.A11)
JTAG_TMS: TIDA-00204_revE3_JTAGUSB (J8.1 R142.2), TIDA-00204_revE3_Sitara_SC_0 (U15.C11)
JTAG_TRSTn: TIDA-00204_revE3_JTAGUSB (J8.2 R143.2 R153.2), TIDA-00204_revE3_Sitara_SC_0 (U15.B10)
MDIO_CLK_1: TIDA-00204_revE3_PHY_1 (U6.20), TIDA-00204_revE3_Sitara_SC_0 (R73.2)
MDIO_CLK_2: TIDA-00204_revE3_PHY_2 (U12.20), TIDA-00204_revE3_Sitara_SC_0 (R72.2)
MDIO_DATA_1: TIDA-00204_revE3_PHY_1 (U6.21), TIDA-00204_revE3_Sitara_SC_0 (R74.2)
MDIO_DATA_2: TIDA-00204_revE3_PHY_2 (U12.21), TIDA-00204_revE3_Sitara_SC_0 (R75.2)
MMC1_CLK: TIDA-00204_revE3_Memory (J6.5 R123.1 U18.8), TIDA-00204_revE3_Sitara_SC_0 (U15.U9)
MMC1_CMD: TIDA-00204_revE3_Memory (J6.3 R122.1 U18.1), TIDA-00204_revE3_Sitara_SC_0 (U15.V9)
MMC1_DAT0: TIDA-00204_revE3_Memory (J6.7 R124.1 U18.7), TIDA-00204_revE3_Sitara_SC_0 (U15.U7)
MMC1_DAT1: TIDA-00204_revE3_Memory (J6.8 R125.1 U18.6), TIDA-00204_revE3_Sitara_SC_0 (U15.V7)
MMC1_DAT2: TIDA-00204_revE3_Memory (J6.1 R120.1 U18.3), TIDA-00204_revE3_Sitara_SC_0 (U15.R8)
MMC1_DAT3: TIDA-00204_revE3_Memory (J6.2 R121.1 U18.2), TIDA-00204_revE3_Sitara_SC_0 (U15.T8)
PHY1_CLKOUT: TIDA-00204_revE3_PHY_1 (R35.2), TIDA-00204_revE3_PHY_2 (R63.1)
PHY1_INTPWDN: TIDA-00204_revE3_PHY_1 (R29.2 U6.60), TIDA-00204_revE3_Sitara_SC_0 (U15.G18)
PHY1_RX1588: TIDA-00204_revE3_PHY_1 (U6.49), TIDA-00204_revE3_Sitara_SC_0 (U15.C15)
PHY1_TX1588: TIDA-00204_revE3_PHY_1 (R28.2 R31.2 U6.50), TIDA-00204_revE3_Sitara_SC_0 (U15.C18)
PHY2_INTPWDN: TIDA-00204_revE3_PHY_2 (R55.2 U12.60), TIDA-00204_revE3_Sitara_SC_0 (U15.V13)
PHY2_RX1588: TIDA-00204_revE3_PHY_2 (U12.49), TIDA-00204_revE3_Sitara_SC_0 (U15.U13)
PHY2_TX1588: TIDA-00204_revE3_PHY_2 (R56.2 R61.2 U12.50), TIDA-00204_revE3_Sitara_SC_0 (U15.E15)
PHY_RESETn: TIDA-00204_revE3_PHY_1 (U6.59 U11.4), TIDA-00204_revE3_PHY_2 (U12.59)
PMIC_PWR_EN: TIDA-00204_revE3_PS_2 (U13.1), TIDA-00204_revE3_Sitara_SC_0 (U15.C6)
PMIC_RESETOUTn: TIDA-00204_revE3_PS_2 (R67.2 U13.40), TIDA-00204_revE3_Sitara_SC_0 (C191.2 U15.B15)
RGMII1_RXCLK: TIDA-00204_revE3_PHY_1 (R20.2), TIDA-00204_revE3_Sitara_SC_0 (U15.L18)
RGMII1_RXCTRL: TIDA-00204_revE3_PHY_1 (R19.1), TIDA-00204_revE3_Sitara_SC_0 (U15.J17)
RGMII1_RXD0: TIDA-00204_revE3_PHY_1 (R20.4), TIDA-00204_revE3_Sitara_SC_0 (U15.M16)
RGMII1_RXD1: TIDA-00204_revE3_PHY_1 (R20.5), TIDA-00204_revE3_Sitara_SC_0 (U15.L15)
RGMII1_RXD2: TIDA-00204_revE3_PHY_1 (R20.6), TIDA-00204_revE3_Sitara_SC_0 (U15.L16)
RGMII1_RXD3: TIDA-00204_revE3_PHY_1 (R20.7), TIDA-00204_revE3_Sitara_SC_0 (U15.L17)
RGMII1_TXCLK: TIDA-00204_revE3_PHY_1 (U6.40), TIDA-00204_revE3_Sitara_SC_0 (R69.10)
RGMII1_TXCTRL: TIDA-00204_revE3_PHY_1 (U6.52), TIDA-00204_revE3_Sitara_SC_0 (R69.14)
RGMII1_TXD0: TIDA-00204_revE3_PHY_1 (U6.38), TIDA-00204_revE3_Sitara_SC_0 (R69.12)
RGMII1_TXD1: TIDA-00204_revE3_PHY_1 (U6.37), TIDA-00204_revE3_Sitara_SC_0 (R69.9)
RGMII1_TXD2: TIDA-00204_revE3_PHY_1 (U6.36), TIDA-00204_revE3_Sitara_SC_0 (R69.11)
RGMII1_TXD3: TIDA-00204_revE3_PHY_1 (U6.35), TIDA-00204_revE3_Sitara_SC_0 (R69.13)
RGMII2_RXCLK: TIDA-00204_revE3_PHY_2 (R44.1), TIDA-00204_revE3_Sitara_SC_0 (U15.T15)
RGMII2_RXCTRL: TIDA-00204_revE3_PHY_2 (R43.1), TIDA-00204_revE3_Sitara_SC_0 (U15.V14)
RGMII2_RXD0: TIDA-00204_revE3_PHY_2 (R46.1), TIDA-00204_revE3_Sitara_SC_0 (U15.V17)
RGMII2_RXD1: TIDA-00204_revE3_PHY_2 (R47.1), TIDA-00204_revE3_Sitara_SC_0 (U15.T16)
RGMII2_RXD2: TIDA-00204_revE3_PHY_2 (R50.1), TIDA-00204_revE3_Sitara_SC_0 (U15.U16)
RGMII2_RXD3: TIDA-00204_revE3_PHY_2 (R51.1), TIDA-00204_revE3_Sitara_SC_0 (U15.V16)
RGMII2_TXCLK: TIDA-00204_revE3_PHY_2 (U12.40), TIDA-00204_revE3_Sitara_SC_0 (R82.2)
RGMII2_TXCTRL: TIDA-00204_revE3_PHY_2 (U12.52), TIDA-00204_revE3_Sitara_SC_0 (R77.2)
RGMII2_TXD0: TIDA-00204_revE3_PHY_2 (U12.38), TIDA-00204_revE3_Sitara_SC_0 (R81.2)
RGMII2_TXD1: TIDA-00204_revE3_PHY_2 (U12.37), TIDA-00204_revE3_Sitara_SC_0 (R80.2)
RGMII2_TXD2: TIDA-00204_revE3_PHY_2 (U12.36), TIDA-00204_revE3_Sitara_SC_0 (R79.2)
RGMII2_TXD3: TIDA-00204_revE3_PHY_2 (U12.35), TIDA-00204_revE3_Sitara_SC_0 (R78.2)
SYS_RESETn: TIDA-00204_revE3_JTAGUSB (R164.1 U24.4), TIDA-00204_revE3_PHY_1 (U11.2), TIDA-00204_revE3_Sitara_SC_0 (R70.1 R71.1 U15.A10)

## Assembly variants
Complete: all parts fitted
001: not fitted C12 C34 C62 C238 C242 C252 C253 C254 C255 C256 C257 C258 C259 J8 L13 L14 R35 R36 R63 R65 R83 R85 R86 R87 R88 R89 R90 R91 R92 R93 R97 R98 R102 R112 R113 R114 R151 R159 R160 R161 R162 R163 R164 R166 R167 R168 R169 R171 R173 R175 R176 R177 R178 R179 R180 R181 R182 R183 U8 U10 U25 Y6
002: not fitted C12 C31 C32 C34 C60 C61 C62 C192 C193 C238 C242 J8 R35 R36 R63 R65 R83 R85 R86 R87 R88 R89 R90 R91 R92 R93 R97 R98 R102 R112 R113 R114 R151 R159 R160 R161 R162 R163 R164 R168 R170 R172 R174 R179 R180 R181 U8 U10 Y1 Y2 Y3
